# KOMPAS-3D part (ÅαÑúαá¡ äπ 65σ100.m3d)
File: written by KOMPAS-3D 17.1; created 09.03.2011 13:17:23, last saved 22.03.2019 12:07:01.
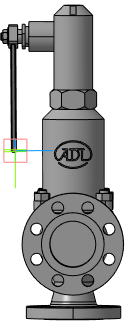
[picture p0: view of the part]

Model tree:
1. Плоскость XY
2. Плоскость ZX
3. Плоскость ZY
4. Ось X
5. Ось Y
6. Ось Z
7. Начало координат
8. Операция без истории:2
